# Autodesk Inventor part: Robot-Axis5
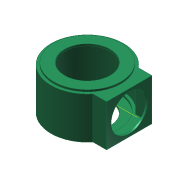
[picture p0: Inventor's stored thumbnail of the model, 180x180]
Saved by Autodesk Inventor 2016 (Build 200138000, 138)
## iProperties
Shininess: 21.0
Length Units: 11269
Angle Units: 11279
Time Units: 11290
Mass Units: 11283
Length Display Precision: 3
Angle Display Precision: 2
Created: 2001-08
Part Number: Robot-Axis5
Document SubType Name: ﾓﾃﾞﾘﾝｸﾞ
Designer: Administrator
Density: 1 g/cm^3
Material: Generic
Mass: 36.0469 g
Surface Area: 369.548 cm^2
Volume: 36.0469 cm^3
Appearance: Sea Green
Density: 0.0
Volumn: 0.0
Area: 0.0
PropertySet Name: Model Information
Control State: 0
Master: False
Checked Out: False
Author: Administrator
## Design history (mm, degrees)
sketch "ｽｹｯﾁ1"
  geometry: C1 r 40 at (0, 0)
  constraints: 1 centre point
  dimensions: "d0" = 80 diameter of C1
extrude "押し出し1" new body sketch "ｽｹｯﾁ1" taper "d2" = 0 deg
sketch "ｽｹｯﾁ2"
  geometry: C1 r 40 at (0, 0) reference; C2 r 37 at (0, 0)
  constraints: 1 centre point
  dimensions: "d3" = 3 radial gap between concentric circles of C1 C2
extrude "押し出し2" join sketch "ｽｹｯﾁ2" distance "d4" = 2; taper "d5" = 0 deg
node "作業平面1"
sketch "ｽｹｯﾁ3"
  geometry: L1 (-37, -25)-(37, -25) reference; L2 (40, -23)-(-40, -23) reference; L3 (-25, 23)-(25, 23); L4 (25, 23)-(25, -23); L5 (25, -23)-(-25, -23); L6 (-25, -23)-(-25, 23); L7 (-25, 0)-(25, 0); L8 (0, 23)-(0, -23); L9 (0, -23)-(0, 24.715)
  constraints: 14 end point, 6 midpoint, 2 collinear, 2 parallel, 2 perpendicular, 1 horizontal, 1 point on line
  dimensions: "d6" = 50 distance of L3.start L3.end; "d7" = 46 distance of L5.end L3.start; "d8" = 25 distance between parallel lines of L6 L8
extrude "押し出し3" join sketch "ｽｹｯﾁ3" distance "d9" = 46.2; taper "d10" = 0 deg
node "作業軸1"
workaxis "Work Axis2"
  workplane "Work Plane2"
  workplane "Work Plane3"
shell "Shell1" dims "d20" = 2
sketch "Sketch7"
  geometry: C1 r 37 at (0, 0) reference
hole "Hole1" sketch "Sketch7" at (0, 0) diameter "d21" = 50; stored, may be unused: countersink angle "d25" = 82 deg, drill point angle "d27" = 118 deg; dims "d22" = 6, "d23" = 4, "d24" = 2, "d26" = 8
sketch "Sketch8"
  geometry: 1 further point
hole "Hole2" sketch "Sketch8" at (0, 0) diameter "d28" = 40; stored, may be unused: countersink angle "d32" = 82 deg, drill point angle "d34" = 118 deg; dims "d29" = 6, "d30" = 4, "d31" = 2, "d33" = 2
body "Solid1"
mirror "Mirror1"
sketch "Sketch4"
  geometry: 1 further point
